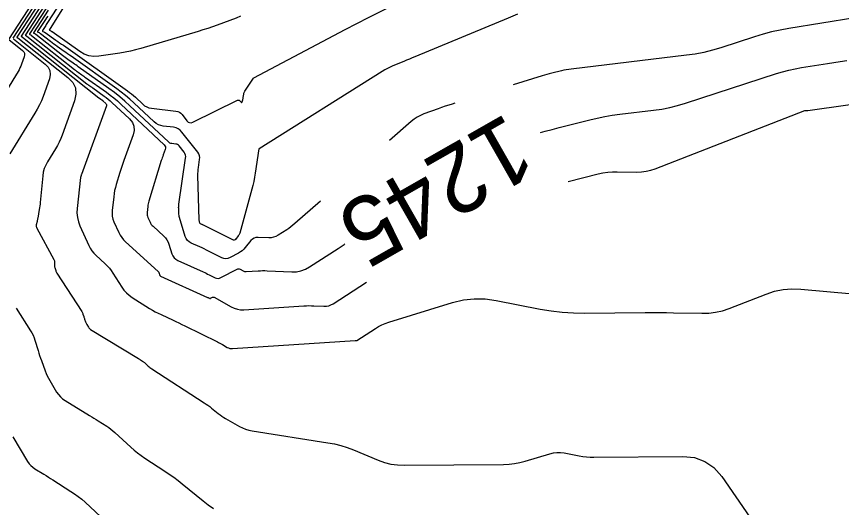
# Model space of a CAD drawing. Extents: x 658976 to 668721, y 639543 to 647196.
# Drawn here: x 662136.9 to 662210.2, y 641754.9 to 641798.6 of the extents above; entities that cross this region are included whole.
import ezdxf

# ---------------------------------------------------------------- set-up
doc = ezdxf.new("R2010")
doc.units = 0
for name, color, linetype in [('Ex_Contour Labels', 7, 'Continuous'), ('Ex_Major Contours', 7, 'Continuous'), ('Ex_Minor Contours', 7, 'Continuous')]:
    doc.layers.add(name, color=color, linetype=linetype)

msp = doc.modelspace()

# ---------------------------------------------------------------- linework, layer by layer
at = {"layer": 'Ex_Major Contours'}
for points in [[(662143.492, 641807.763), (662136.193, 641796.529)], [(662140.069, 641800.113), (662138.06, 641797.022), (662138.052, 641797.005), (662138.052, 641796.99), (662138.06, 641796.977), (662138.076, 641796.966), (662138.154, 641796.929), (662138.174, 641796.919), (662138.192, 641796.908), (662138.21, 641796.896), (662138.228, 641796.883), (662142.065, 641793.837), (662142.143, 641793.776), (662142.222, 641793.716), (662142.302, 641793.658), (662142.383, 641793.601), (662142.707, 641793.376), (662142.789, 641793.32), (662142.87, 641793.264), (662142.95, 641793.207), (662143.031, 641793.15), (662144.897, 641791.825), (662145.23, 641791.579), (662145.554, 641791.323), (662145.87, 641791.055), (662146.176, 641790.777), (662150.01, 641787.169), (662150.087, 641787.075), (662150.13, 641786.974), (662150.137, 641786.864), (662150.11, 641786.746), (662149.932, 641786.257), (662149.888, 641786.134), (662149.846, 641786.011), (662149.805, 641785.887), (662149.766, 641785.763), (662148.665, 641782.16), (662148.631, 641782.039), (662148.602, 641781.916), (662148.58, 641781.792), (662148.563, 641781.666), (662148.506, 641781.139), (662148.501, 641781.026), (662148.511, 641780.916), (662148.536, 641780.808), (662148.575, 641780.703), (662148.764, 641780.287), (662148.816, 641780.186), (662148.877, 641780.092), (662148.947, 641780.005), (662149.027, 641779.924), (662149.995, 641779.037), (662150.144, 641778.882), (662150.268, 641778.711), (662150.368, 641778.526), (662150.444, 641778.325), (662150.7, 641777.49), (662150.781, 641777.297), (662150.895, 641777.132), (662151.043, 641776.998), (662151.225, 641776.893), (662153.484, 641775.869), (662153.617, 641775.808), (662153.75, 641775.745), (662153.882, 641775.682), (662154.014, 641775.617), (662154.54, 641775.357), (662154.671, 641775.308), (662154.802, 641775.293), (662154.932, 641775.311), (662155.062, 641775.363), (662156.492, 641776.12), (662156.559, 641776.147), (662156.626, 641776.155), (662156.693, 641776.145), (662156.76, 641776.117), (662157.025, 641775.966), (662157.092, 641775.934), (662157.162, 641775.912), (662157.235, 641775.901), (662157.31, 641775.901), (662158.364, 641775.97), (662158.565, 641775.98), (662158.766, 641775.985), (662158.967, 641775.984), (662159.168, 641775.978), (662161.349, 641775.878), (662161.771, 641775.891), (662162.176, 641775.966), (662162.564, 641776.105), (662162.935, 641776.307), (662165.48, 641777.952), (662166.018, 641778.314), (662166.072, 641778.353)], [(662136.215, 641796.511), (662137.43, 641795.547), (662137.545, 641795.429), (662137.61, 641795.296), (662137.624, 641795.149), (662137.589, 641794.988), (662137.347, 641794.315), (662137.282, 641794.149), (662137.209, 641793.986), (662137.128, 641793.828), (662137.038, 641793.674), (662132.871, 641786.922)], [(662183.456, 641788.241), (662183.869, 641788.36), (662184.493, 641788.531), (662185.119, 641788.694), (662187.833, 641789.378), (662188.497, 641789.534), (662189.165, 641789.669), (662189.836, 641789.781), (662190.512, 641789.873), (662193.503, 641790.229), (662194.224, 641790.333), (662194.937, 641790.471), (662195.642, 641790.645), (662196.34, 641790.853), (662204.415, 641793.482), (662204.969, 641793.651), (662205.527, 641793.797), (662206.091, 641793.921), (662206.66, 641794.023), (662208.947, 641794.388), (662209.519, 641794.479), (662210.09, 641794.569), (662210.663, 641794.658)], [(662136.572, 641761.221), (662137.89, 641759.026), (662138.021, 641758.835), (662138.171, 641758.664), (662138.342, 641758.512), (662138.533, 641758.381), (662139.335, 641757.894), (662139.536, 641757.772), (662139.735, 641757.649), (662139.934, 641757.524), (662140.132, 641757.398), (662141.737, 641756.373), (662142.065, 641756.153), (662142.382, 641755.919), (662142.689, 641755.672), (662142.985, 641755.41), (662146.242, 641752.404)]]:
    msp.add_lwpolyline(points, dxfattribs=at)
at = {"layer": 'Ex_Minor Contours'}
for points in [[(662145.378, 641806.84), (662139.709, 641798.111), (662139.655, 641798.027), (662139.601, 641797.943), (662139.548, 641797.858), (662139.495, 641797.772), (662139.212, 641797.31), (662139.201, 641797.287), (662139.202, 641797.266), (662139.213, 641797.249), (662139.234, 641797.235), (662139.34, 641797.185), (662139.366, 641797.171), (662139.392, 641797.157), (662139.417, 641797.142), (662139.442, 641797.126), (662140.398, 641796.464), (662140.565, 641796.348), (662140.732, 641796.232), (662140.898, 641796.114), (662141.064, 641795.997), (662146.771, 641791.944), (662146.951, 641791.812), (662147.125, 641791.674), (662147.295, 641791.53), (662147.461, 641791.379), (662148.112, 641790.767), (662148.282, 641790.629), (662148.467, 641790.524), (662148.666, 641790.45), (662148.881, 641790.408), (662151.062, 641790.15), (662151.225, 641790.116), (662151.371, 641790.052), (662151.502, 641789.959), (662151.615, 641789.838), (662152.038, 641789.294), (662152.15, 641789.184), (662152.274, 641789.127), (662152.411, 641789.123), (662152.559, 641789.172), (662156.543, 641791.111), (662156.587, 641791.125), (662156.629, 641791.126), (662156.669, 641791.112), (662156.706, 641791.084), (662156.849, 641790.943), (662156.882, 641790.918), (662156.91, 641790.914), (662156.932, 641790.931), (662156.948, 641790.97), (662157.002, 641791.166), (662157.015, 641791.215), (662157.026, 641791.264), (662157.035, 641791.314), (662157.044, 641791.364), (662157.088, 641791.668), (662157.101, 641791.734), (662157.121, 641791.797), (662157.148, 641791.858), (662157.182, 641791.916), (662157.949, 641793.076), (662157.953, 641793.082), (662157.957, 641793.092), (662157.959, 641793.094), (662157.96, 641793.095), (662157.962, 641793.096), (662157.964, 641793.096), (662157.981, 641793.098), (662157.985, 641793.098), (662157.989, 641793.099), (662157.992, 641793.1), (662157.995, 641793.102), (662164.078, 641796.344), (662165.095, 641796.881), (662166.115, 641797.412), (662167.138, 641797.937), (662168.165, 641798.455), (662178.286, 641803.518)], [(662142.728, 641806.111), (662136.567, 641796.628)], [(662141.964, 641804.459), (662136.94, 641796.726), (662136.936, 641796.718), (662136.936, 641796.711), (662136.94, 641796.705), (662136.947, 641796.7), (662136.985, 641796.682), (662136.994, 641796.677), (662137.003, 641796.672), (662137.012, 641796.666), (662137.02, 641796.66), (662141.469, 641793.128), (662141.89, 641792.695), (662142.128, 641792.209), (662142.182, 641791.671), (662142.052, 641791.081), (662140.952, 641788.021), (662140.829, 641787.706), (662140.69, 641787.398), (662140.536, 641787.097), (662140.365, 641786.805), (662139.652, 641785.649), (662139.492, 641785.354), (662139.368, 641785.046), (662139.282, 641784.727), (662139.231, 641784.395), (662139.008, 641782.041), (662138.991, 641781.886), (662138.972, 641781.731), (662138.949, 641781.576), (662138.923, 641781.421), (662138.786, 641780.648), (662138.772, 641780.572), (662138.757, 641780.497), (662138.741, 641780.422), (662138.723, 641780.347), (662138.653, 641780.048), (662138.642, 641779.974), (662138.645, 641779.902), (662138.661, 641779.832), (662138.691, 641779.764), (662140.229, 641776.964), (662140.254, 641776.91), (662140.271, 641776.855), (662140.281, 641776.797), (662140.282, 641776.738), (662140.273, 641776.496), (662140.273, 641776.436), (662140.278, 641776.376), (662140.288, 641776.317), (662140.302, 641776.259), (662140.383, 641775.989), (662140.404, 641775.925), (662140.429, 641775.864), (662140.459, 641775.805), (662140.494, 641775.747), (662142.701, 641772.344), (662142.732, 641772.292), (662142.759, 641772.239), (662142.782, 641772.183), (662142.802, 641772.126), (662142.871, 641771.894), (662142.888, 641771.836), (662142.907, 641771.778), (662142.926, 641771.721), (662142.947, 641771.663), (662143.032, 641771.43), (662143.054, 641771.373), (662143.079, 641771.317), (662143.107, 641771.262), (662143.138, 641771.209), (662143.293, 641770.95), (662143.333, 641770.892), (662143.379, 641770.84), (662143.43, 641770.794), (662143.488, 641770.754), (662147.725, 641768.186), (662147.771, 641768.158), (662147.817, 641768.13), (662147.863, 641768.101), (662147.908, 641768.072), (662148.091, 641767.955), (662148.136, 641767.925), (662148.179, 641767.893), (662148.221, 641767.859), (662148.262, 641767.824), (662148.605, 641767.506), (662148.677, 641767.443), (662148.752, 641767.382), (662148.828, 641767.325), (662148.908, 641767.272), (662153.582, 641764.244), (662153.746, 641764.134), (662153.907, 641764.021), (662154.064, 641763.903), (662154.219, 641763.78), (662154.83, 641763.282), (662154.985, 641763.161), (662155.145, 641763.047), (662155.31, 641762.94), (662155.479, 641762.839), (662156.709, 641762.144), (662156.976, 641762.009), (662157.251, 641761.899), (662157.536, 641761.814), (662157.829, 641761.754), (662164.561, 641760.693), (662165.145, 641760.584), (662165.72, 641760.44), (662166.286, 641760.263), (662166.842, 641760.052), (662169.046, 641759.141), (662169.603, 641758.943), (662170.171, 641758.802), (662170.75, 641758.719), (662171.341, 641758.695), (662180.176, 641758.761), (662180.665, 641758.782), (662181.148, 641758.838), (662181.626, 641758.93), (662182.098, 641759.056), (662184.277, 641759.724), (662184.598, 641759.801), (662184.921, 641759.838), (662185.246, 641759.835), (662185.573, 641759.79), (662186.885, 641759.532), (662187.213, 641759.476), (662187.544, 641759.437), (662187.876, 641759.415), (662188.209, 641759.409), (662196.092, 641759.48), (662197.135, 641759.376), (662198.059, 641759.043), (662198.865, 641758.481), (662199.553, 641757.691), (662202.068, 641754.073)], [(662141.201, 641802.808), (662137.313, 641796.825), (662137.308, 641796.813), (662137.308, 641796.804), (662137.313, 641796.795), (662137.324, 641796.789), (662137.375, 641796.764), (662137.387, 641796.757), (662137.4, 641796.75), (662137.411, 641796.742), (662137.423, 641796.734), (662144.225, 641791.335), (662144.232, 641791.33), (662144.238, 641791.324), (662144.245, 641791.319), (662144.252, 641791.314), (662144.288, 641791.29), (662144.309, 641791.275), (662144.472, 641791.16), (662144.501, 641791.138), (662144.529, 641791.116), (662144.556, 641791.092), (662144.583, 641791.068), (662144.833, 641790.833), (662144.874, 641790.783), (662144.897, 641790.729), (662144.901, 641790.671), (662144.886, 641790.608), (662142.67, 641784.534), (662142.662, 641784.51), (662142.654, 641784.486), (662142.646, 641784.462), (662142.638, 641784.438), (662142.609, 641784.342), (662142.602, 641784.317), (662142.596, 641784.293), (662142.592, 641784.268), (662142.588, 641784.243), (662142.291, 641781.507), (662142.273, 641781.106), (662142.309, 641780.712), (662142.397, 641780.327), (662142.539, 641779.951), (662143.322, 641778.221), (662143.447, 641777.978), (662143.595, 641777.751), (662143.764, 641777.54), (662143.957, 641777.346), (662144.77, 641776.6), (662144.966, 641776.408), (662145.148, 641776.204), (662145.316, 641775.989), (662145.471, 641775.761), (662146.248, 641774.529), (662146.44, 641774.259), (662146.658, 641774.016), (662146.902, 641773.798), (662147.172, 641773.607), (662148.73, 641772.629), (662148.979, 641772.479), (662149.232, 641772.336), (662149.489, 641772.202), (662149.75, 641772.075), (662150.805, 641771.585), (662151.068, 641771.462), (662151.33, 641771.337), (662151.592, 641771.21), (662151.853, 641771.082), (662154.744, 641769.653), (662154.857, 641769.596), (662154.969, 641769.537), (662155.08, 641769.477), (662155.19, 641769.416), (662155.63, 641769.166), (662155.742, 641769.113), (662155.858, 641769.077), (662155.979, 641769.059), (662156.103, 641769.058), (662166.976, 641769.769), (662166.989, 641769.77), (662167.002, 641769.77), (662167.015, 641769.77), (662167.028, 641769.77), (662167.079, 641769.767), (662167.092, 641769.768), (662167.104, 641769.77), (662167.116, 641769.774), (662167.127, 641769.78), (662168.785, 641770.852), (662169.07, 641771.022), (662169.364, 641771.172), (662169.668, 641771.301), (662169.982, 641771.409), (662175.645, 641773.144), (662176.602, 641773.375), (662177.565, 641773.486), (662178.535, 641773.475), (662179.51, 641773.343), (662183.425, 641772.572), (662184.406, 641772.405), (662185.392, 641772.288), (662186.383, 641772.221), (662187.378, 641772.205), (662192.769, 641772.254), (662193.396, 641772.257), (662194.023, 641772.256), (662194.649, 641772.251), (662195.276, 641772.241), (662197.782, 641772.194), (662198.404, 641772.211), (662199.014, 641772.289), (662199.615, 641772.426), (662200.204, 641772.623), (662203.5, 641773.903), (662204.251, 641774.147), (662205.014, 641774.301), (662205.79, 641774.364), (662206.578, 641774.337), (662213.517, 641773.711)], [(662156.812, 641798.587), (662156.41, 641798.408), (662154.729, 641797.794), (662154.308, 641797.644), (662153.884, 641797.5), (662153.458, 641797.363), (662153.031, 641797.232), (662147.937, 641795.717), (662147.481, 641795.591), (662147.023, 641795.481), (662146.56, 641795.388), (662146.094, 641795.311), (662144.222, 641795.039), (662143.764, 641795.013), (662143.327, 641795.074), (662142.911, 641795.219), (662142.515, 641795.45), (662140.058, 641797.195), (662140.039, 641797.208), (662140.02, 641797.222), (662140, 641797.235), (662139.981, 641797.249), (662139.87, 641797.326), (662139.865, 641797.329), (662139.858, 641797.332), (662139.846, 641797.338), (662139.844, 641797.34), (662139.842, 641797.342), (662139.842, 641797.344), (662139.844, 641797.347), (662143.106, 641802.656)], [(662140.437, 641801.156), (662137.687, 641796.923), (662137.68, 641796.909), (662137.68, 641796.897), (662137.687, 641796.886), (662137.7, 641796.877), (662137.765, 641796.846), (662137.78, 641796.838), (662137.796, 641796.829), (662137.811, 641796.819), (662137.825, 641796.808), (662143.145, 641792.586), (662143.187, 641792.553), (662143.23, 641792.52), (662143.274, 641792.489), (662143.317, 641792.458), (662143.494, 641792.336), (662143.538, 641792.305), (662143.582, 641792.274), (662143.626, 641792.243), (662143.67, 641792.212), (662144.684, 641791.492), (662144.865, 641791.359), (662145.042, 641791.219), (662145.213, 641791.074), (662145.379, 641790.923), (662146.938, 641789.456), (662147.194, 641789.146), (662147.335, 641788.809), (662147.361, 641788.445), (662147.271, 641788.053), (662146.44, 641785.776), (662146.345, 641785.512), (662146.255, 641785.247), (662146.167, 641784.981), (662146.084, 641784.713), (662145.756, 641783.642), (662145.681, 641783.372), (662145.618, 641783.101), (662145.568, 641782.826), (662145.532, 641782.549), (662145.398, 641781.323), (662145.387, 641781.066), (662145.41, 641780.814), (662145.466, 641780.568), (662145.557, 641780.327), (662145.988, 641779.375), (662146.107, 641779.144), (662146.246, 641778.929), (662146.407, 641778.729), (662146.589, 641778.545), (662149.48, 641775.896), (662149.508, 641775.867), (662149.531, 641775.836), (662149.549, 641775.802), (662149.563, 641775.764), (662149.61, 641775.611), (662149.625, 641775.575), (662149.646, 641775.545), (662149.674, 641775.52), (662149.707, 641775.501), (662153.883, 641773.607), (662153.905, 641773.597), (662153.927, 641773.587), (662153.949, 641773.576), (662153.97, 641773.566), (662154.056, 641773.523), (662154.078, 641773.515), (662154.099, 641773.513), (662154.121, 641773.516), (662154.142, 641773.524), (662154.324, 641773.62), (662154.361, 641773.635), (662154.398, 641773.64), (662154.435, 641773.634), (662154.472, 641773.618), (662155.978, 641772.765), (662156.246, 641772.637), (662156.523, 641772.551), (662156.811, 641772.507), (662157.108, 641772.506), (662162.441, 641772.855), (662162.662, 641772.866), (662162.884, 641772.871), (662163.105, 641772.87), (662163.327, 641772.863), (662164.214, 641772.823), (662164.432, 641772.829), (662164.64, 641772.868), (662164.84, 641772.94), (662165.031, 641773.044), (662168.003, 641774.965)], [(662163.903, 641782.156), (662161.627, 641780.159), (662161.454, 641780.013), (662161.276, 641779.873), (662161.093, 641779.74), (662160.905, 641779.614), (662160.14, 641779.119), (662159.947, 641779.014), (662159.745, 641778.942), (662159.535, 641778.902), (662159.315, 641778.896), (662158.366, 641778.939), (662158.177, 641778.928), (662158.006, 641778.876), (662157.854, 641778.783), (662157.719, 641778.649), (662157.219, 641778.033), (662157.088, 641777.887), (662156.944, 641777.756), (662156.787, 641777.64), (662156.618, 641777.539), (662155.871, 641777.144), (662155.688, 641777.071), (662155.504, 641777.045), (662155.32, 641777.066), (662155.135, 641777.134), (662153.957, 641777.719), (662153.766, 641777.813), (662153.574, 641777.905), (662153.381, 641777.995), (662153.187, 641778.084), (662152.41, 641778.437), (662152.232, 641778.539), (662152.088, 641778.671), (662151.976, 641778.831), (662151.897, 641779.02), (662151.382, 641780.7), (662151.356, 641780.796), (662151.337, 641780.893), (662151.324, 641780.991), (662151.318, 641781.09), (662151.307, 641781.488), (662151.306, 641781.587), (662151.31, 641781.687), (662151.318, 641781.786), (662151.33, 641781.884), (662151.921, 641785.968), (662151.929, 641786.112), (662151.908, 641786.249), (662151.858, 641786.378), (662151.781, 641786.5), (662151.34, 641787.067), (662151.281, 641787.13), (662151.214, 641787.178), (662151.138, 641787.211), (662151.053, 641787.229), (662150.698, 641787.271), (662150.612, 641787.287), (662150.533, 641787.317), (662150.459, 641787.359), (662150.391, 641787.414), (662146.972, 641790.631), (662146.526, 641791.037), (662146.067, 641791.426), (662145.595, 641791.8), (662145.109, 641792.157), (662142.392, 641794.087), (662142.274, 641794.17), (662142.157, 641794.253), (662142.039, 641794.335), (662141.921, 641794.417), (662141.448, 641794.745), (662141.33, 641794.828), (662141.214, 641794.912), (662141.099, 641794.999), (662140.986, 641795.087), (662138.63, 641796.957), (662138.61, 641796.972), (662138.589, 641796.986), (662138.567, 641796.999), (662138.544, 641797.011), (662138.452, 641797.055), (662138.433, 641797.068), (662138.424, 641797.083), (662138.424, 641797.1), (662138.433, 641797.12), (662139.73, 641799.117)], [(662181.402, 641798.768), (662180.577, 641798.404), (662172.302, 641794.981), (662172.056, 641794.879), (662171.81, 641794.777), (662171.563, 641794.675), (662171.317, 641794.572), (662170.332, 641794.163), (662170.088, 641794.056), (662169.849, 641793.939), (662169.616, 641793.812), (662169.387, 641793.675), (662158.46, 641786.813), (662158.454, 641786.81), (662158.447, 641786.807), (662158.422, 641786.799), (662158.42, 641786.797), (662158.42, 641786.796), (662158.105, 641784.633), (662158.047, 641784.273), (662157.977, 641783.915), (662157.897, 641783.56), (662157.806, 641783.207), (662156.73, 641779.303), (662156.709, 641779.239), (662156.682, 641779.179), (662156.648, 641779.121), (662156.608, 641779.067), (662156.377, 641778.782), (662156.364, 641778.767), (662156.349, 641778.754), (662156.333, 641778.742), (662156.316, 641778.732), (662156.245, 641778.694), (662156.227, 641778.687), (662156.209, 641778.684), (662156.191, 641778.686), (662156.173, 641778.693), (662153.444, 641780.046), (662153.422, 641780.057), (662153.399, 641780.068), (662153.376, 641780.079), (662153.353, 641780.09), (662153.261, 641780.131), (662153.24, 641780.143), (662153.223, 641780.159), (662153.21, 641780.178), (662153.201, 641780.2), (662153.154, 641780.354), (662153.145, 641780.388), (662153.138, 641780.422), (662153.133, 641780.457), (662153.131, 641780.492), (662153.021, 641784.429), (662153.02, 641784.609), (662153.026, 641784.788), (662153.041, 641784.967), (662153.063, 641785.145), (662153.166, 641785.857), (662153.174, 641786.031), (662153.149, 641786.195), (662153.09, 641786.351), (662152.996, 641786.498), (662151.601, 641788.293), (662151.448, 641788.457), (662151.273, 641788.581), (662151.076, 641788.667), (662150.858, 641788.713), (662149.938, 641788.822), (662149.716, 641788.865), (662149.509, 641788.942), (662149.318, 641789.051), (662149.142, 641789.193), (662147.33, 641790.898), (662146.967, 641791.229), (662146.593, 641791.546), (662146.208, 641791.85), (662145.812, 641792.141), (662141.753, 641795.024), (662141.599, 641795.133), (662141.444, 641795.242), (662141.289, 641795.35), (662141.134, 641795.458), (662140.513, 641795.888), (662140.358, 641795.997), (662140.206, 641796.108), (662140.055, 641796.222), (662139.906, 641796.338), (662139.033, 641797.031), (662139.009, 641797.049), (662138.985, 641797.065), (662138.96, 641797.08), (662138.934, 641797.093), (662138.828, 641797.144), (662138.806, 641797.158), (662138.796, 641797.175), (662138.796, 641797.196), (662138.807, 641797.219), (662139.392, 641798.12), (662139.495, 641798.278), (662139.598, 641798.437), (662139.7, 641798.596)], [(662211.378, 641798.427), (662205.53, 641797.494), (662204.757, 641797.355), (662203.992, 641797.186), (662203.233, 641796.987), (662202.482, 641796.759), (662199.491, 641795.785), (662198.739, 641795.561), (662197.979, 641795.374), (662197.21, 641795.224), (662196.434, 641795.112), (662186.187, 641793.893), (662185.967, 641793.863), (662185.748, 641793.826), (662185.53, 641793.782), (662185.314, 641793.732), (662184.451, 641793.514), (662184.235, 641793.458), (662184.021, 641793.399), (662183.807, 641793.337), (662183.594, 641793.273), (662181.041, 641792.476)], [(662136.618, 641796.585), (662139.449, 641794.338), (662139.718, 641794.062), (662139.869, 641793.753), (662139.903, 641793.41), (662139.82, 641793.034), (662139.256, 641791.465), (662139.105, 641791.077), (662138.935, 641790.699), (662138.745, 641790.33), (662138.536, 641789.971), (662136.303, 641786.353)], [(662185.926, 641783.909), (662188.585, 641784.579), (662189.003, 641784.67), (662189.424, 641784.732), (662189.849, 641784.767), (662190.276, 641784.773), (662191.993, 641784.74), (662192.418, 641784.752), (662192.836, 641784.805), (662193.247, 641784.899), (662193.651, 641785.034), (662206.953, 641790.199), (662206.973, 641790.205), (662206.993, 641790.209), (662207.013, 641790.211), (662207.034, 641790.21), (662207.117, 641790.202), (662207.138, 641790.201), (662207.159, 641790.201), (662207.18, 641790.202), (662207.201, 641790.205), (662221.006, 641792.17)], [(662175.854, 641790.858), (662175.621, 641790.785), (662175.303, 641790.684), (662174.986, 641790.579), (662174.671, 641790.471), (662174.356, 641790.359), (662173.101, 641789.905), (662172.795, 641789.778), (662172.505, 641789.624), (662172.23, 641789.444), (662171.972, 641789.237), (662170.043, 641787.545)], [(662136.859, 641772.639), (662138.15, 641770.649), (662138.271, 641770.447), (662138.377, 641770.237), (662138.467, 641770.021), (662138.542, 641769.797), (662138.811, 641768.889), (662138.88, 641768.663), (662138.953, 641768.437), (662139.029, 641768.213), (662139.109, 641767.99), (662139.442, 641767.079), (662139.529, 641766.856), (662139.627, 641766.637), (662139.736, 641766.424), (662139.855, 641766.215), (662140.464, 641765.201), (662140.618, 641764.975), (662140.796, 641764.773), (662140.998, 641764.594), (662141.223, 641764.438), (662143.392, 641763.124), (662143.584, 641763.007), (662143.775, 641762.888), (662143.966, 641762.769), (662144.156, 641762.648), (662144.914, 641762.164), (662145.1, 641762.039), (662145.281, 641761.906), (662145.455, 641761.766), (662145.623, 641761.617), (662147.052, 641760.299), (662147.35, 641760.035), (662147.659, 641759.784), (662147.978, 641759.547), (662148.308, 641759.324), (662150.068, 641758.183), (662150.47, 641757.916), (662150.863, 641757.637), (662151.249, 641757.348), (662151.627, 641757.049), (662153.497, 641755.525), (662153.94, 641755.18), (662154.396, 641754.854)]]:
    msp.add_lwpolyline(points, dxfattribs=at)

# ---------------------------------------------------------------- texts
at = {"layer": 'Ex_Contour Labels'}
msp.add_text('1245', height=6, rotation=209.69044, dxfattribs=at).set_placement((662180.503, 641790.055))

doc.saveas('drawing.dxf')
